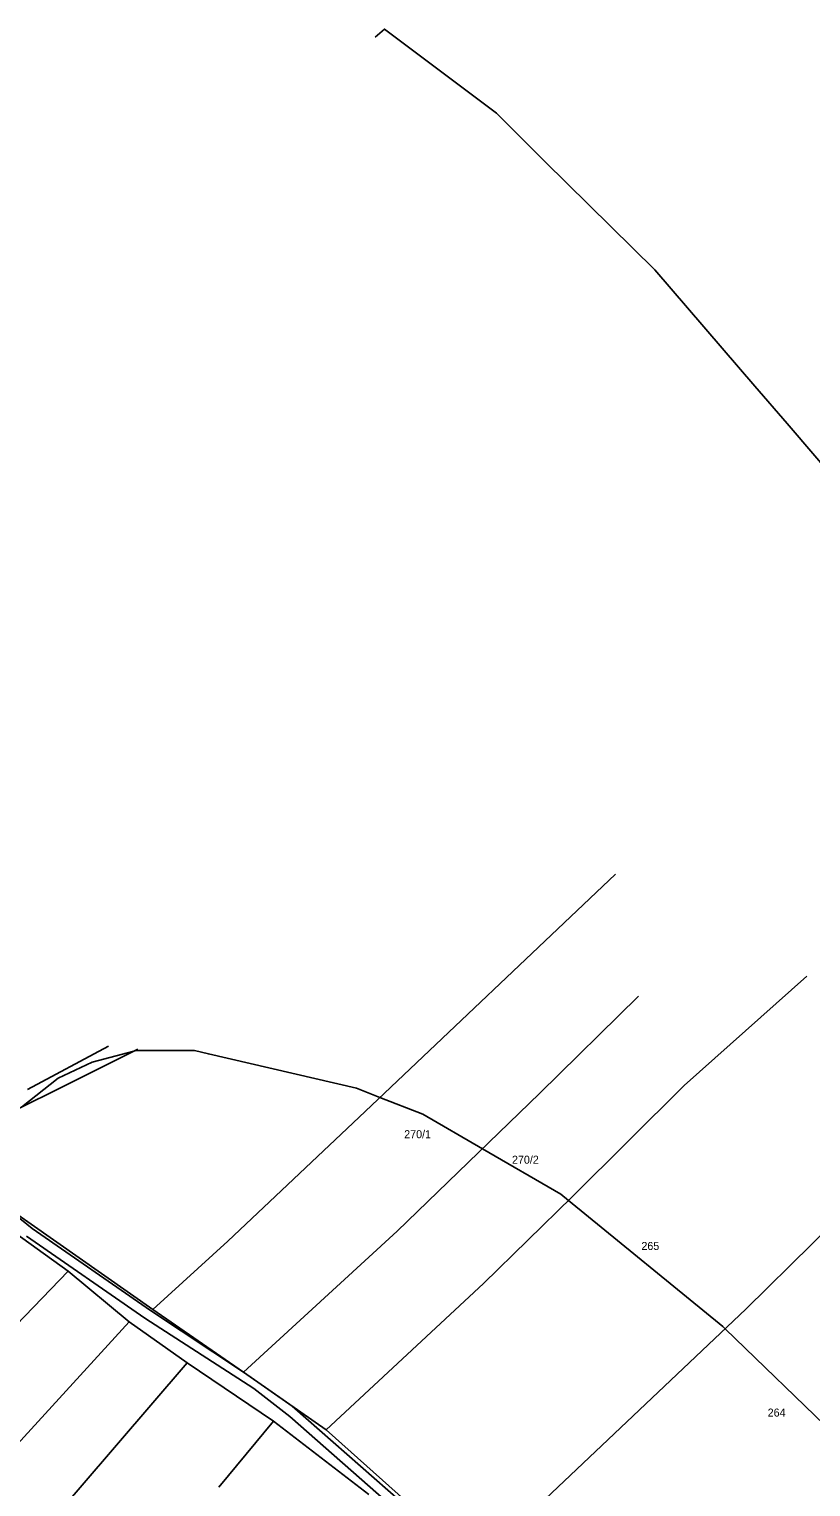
# Model space of a CAD drawing. Extents: x -749173 to -746119, y -1132678 to -1130338.
# Drawn here: x -747370.7 to -747204.7, y -1130801.7 to -1130492 of the extents above; entities that cross this region are included whole.
import ezdxf

# ---------------------------------------------------------------- set-up
doc = ezdxf.new("R2010")
doc.units = 0
for name, color, linetype in [('Vrstva 1', 7, 'Continuous'), ('Vrstva 18', 7, 'Continuous'), ('Vrstva 30', 7, 'Continuous'), ('Vrstva 52', 7, 'Continuous'), ('Vrstva 6', 7, 'Continuous')]:
    doc.layers.add(name, color=color, linetype=linetype)

msp = doc.modelspace()

# ---------------------------------------------------------------- linework, layer by layer
at = {"layer": 'Vrstva 1'}
for points in [[(-747347.62, -1130708.71), (-747389.39, -1130729.51)], [(-747353.84, -1130708.05), (-747371.05, -1130717.26)]]:
    msp.add_lwpolyline(points, dxfattribs=at)
at = {"layer": 'Vrstva 30'}
for p, q in [((-747382.55, -1130736.76), (-747370.07, -1130746.81)), ((-747346.12, -1130765.83), (-747371.27, -1130748.41)), ((-747370.07, -1130746.81), (-747344.98, -1130764.19)), ((-747344.98, -1130764.19), (-747325.19, -1130777.35)), ((-747323.03, -1130780.78), (-747346.12, -1130765.83)), ((-747325.19, -1130777.35), (-747314.84, -1130784.55)), ((-747315.33, -1130786.78), (-747323.03, -1130780.78)), ((-747314.84, -1130784.55), (-747291.65, -1130804.95)), ((-747292.97, -1130806.45), (-747315.33, -1130786.78))]:
    msp.add_line(p, q, dxfattribs=at)
at = {"layer": 'Vrstva 52'}
for points in [[(-747199.23, -1130588.02), (-747209.31, -1130576.25), (-747209.7, -1130575.8), (-747216.54, -1130567.85), (-747237.81, -1130543.12), (-747261.19, -1130520.12), (-747271.44, -1130509.87), (-747295.25, -1130492), (-747297.22, -1130493.72)], [(-747372.36, -1130721.03), (-747364.56, -1130714.87), (-747357.31, -1130711.5), (-747348.5, -1130709.15), (-747347.94, -1130709), (-747335.62, -1130709), (-747332.63, -1130709.7), (-747301.19, -1130717), (-747299.76, -1130717.56), (-747296.21, -1130718.94), (-747287.12, -1130722.5), (-747274.44, -1130729.85), (-747257.81, -1130739.5), (-747256.14, -1130740.86), (-747223.37, -1130767.62), (-747222.86, -1130768.12), (-747199.56, -1130790.62), (-747192.55, -1130797.55), (-747189.31, -1130800.75), (-747171.06, -1130818.62)]]:
    msp.add_lwpolyline(points, dxfattribs=at)
at = {"layer": 'Vrstva 6'}
for points in [[(-747246.16, -1130671.52), (-747299.36, -1130721.93)], [(-747205.53, -1130693.17), (-747231.61, -1130716.42)], [(-747241.26, -1130697.45), (-747262.3, -1130718.14)], [(-747262.3, -1130718.14), (-747292.58, -1130747.36)], [(-747231.61, -1130716.42), (-747255.36, -1130740.1)], [(-747299.36, -1130721.93), (-747328.49, -1130749.49)], [(-747176.21, -1130722.33), (-747218.45, -1130763.95)], [(-747255.36, -1130740.1), (-747274.24, -1130758.52)], [(-747344.46, -1130764.04), (-747375.72, -1130742.04)], [(-747375.64, -1130746.37), (-747362.47, -1130755.89)], [(-747292.58, -1130747.36), (-747325.19, -1130777.35)], [(-747328.49, -1130749.49), (-747344.46, -1130764.04)], [(-747362.47, -1130755.89), (-747406.54, -1130801.59)], [(-747349.46, -1130766.63), (-747362.47, -1130755.89)], [(-747274.24, -1130758.52), (-747307.66, -1130789.55)], [(-747325.19, -1130777.35), (-747344.46, -1130764.04)], [(-747218.45, -1130763.95), (-747275.7, -1130818.09)], [(-747377.79, -1130797.57), (-747349.46, -1130766.63)], [(-747349.46, -1130766.63), (-747337.16, -1130775.31)], [(-747389.53, -1130836.33), (-747337.16, -1130775.31)], [(-747337.16, -1130775.31), (-747318.79, -1130787.77)], [(-747307.66, -1130789.55), (-747325.19, -1130777.35)], [(-747318.79, -1130787.77), (-747330.4, -1130801.79)], [(-747318.79, -1130787.77), (-747298.57, -1130803.35)], [(-747275.7, -1130818.09), (-747307.66, -1130789.55)]]:
    msp.add_lwpolyline(points, dxfattribs=at)

# ---------------------------------------------------------------- texts
at = {"layer": 'Vrstva 18'}
for s, p in [('270/1', (-747291.05, -1130727.62)), ('270/2', (-747268.15, -1130733.04)), ('265', (-747240.66, -1130751.36)), ('264', (-747213.84, -1130786.76))]:
    msp.add_text(s, height=1.7, dxfattribs=at).set_placement(p)

doc.saveas('drawing.dxf')
